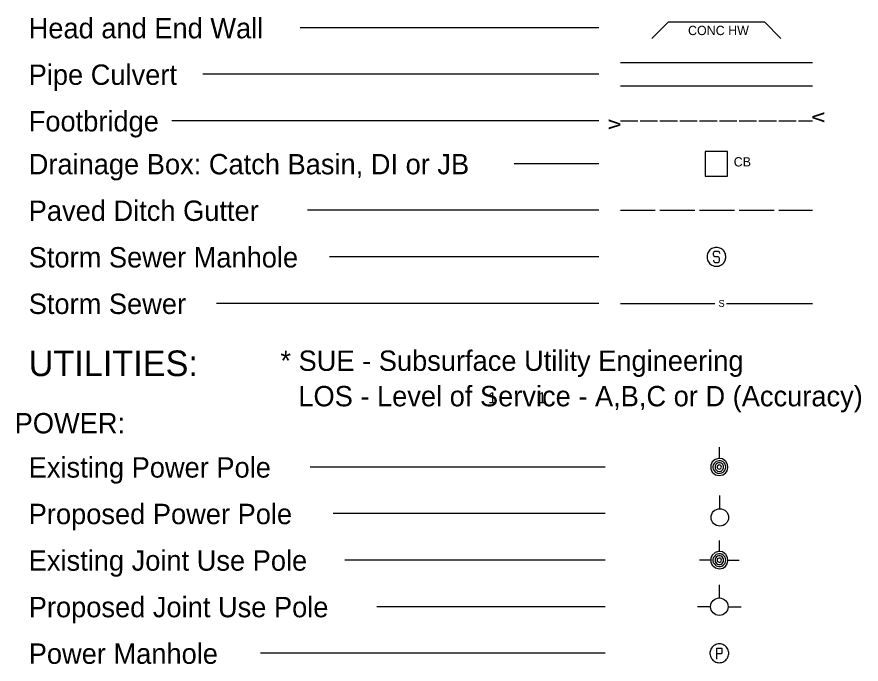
# Model space of a CAD drawing. Extents: x 811137 to 813186, y 647386 to 648494.
# Drawn here: x 812023.6 to 812389.6, y 647926.9 to 648207.5 of the extents above; entities that cross this region are included whole.
import ezdxf

# ---------------------------------------------------------------- set-up
doc = ezdxf.new("R2010")
doc.units = 0
doc.layers.add('Default', color=7, linetype='Continuous')
doc.layers.add('Sheet_Symbology', color=7, linetype='Continuous')

msp = doc.modelspace()

# ---------------------------------------------------------------- linework, layer by layer
at = {"layer": 'Sheet_Symbology'}
for p, q in [((812275.83, 648202.78), (812146.38, 648202.78)), ((812298.88, 648198.17), (812306.02, 648205.3)), ((812306.02, 648205.3), (812347.64, 648205.3)), ((812347.64, 648205.3), (812354.78, 648198.17)), ((812285.21, 648187.65), (812368.45, 648187.65)), ((812275.83, 648182.6), (812104.12, 648182.6)), ((812285.21, 648177.56), (812368.45, 648177.56)), ((812275.83, 648162.42), (812090.71, 648162.42)), ((812285.21, 648162.42), (812292.78, 648162.42)), ((812293.79, 648162.42), (812301.35, 648162.42)), ((812302.36, 648162.42), (812309.93, 648162.42)), ((812310.94, 648162.42), (812318.5, 648162.42)), ((812319.51, 648162.42), (812327.08, 648162.42)), ((812328.09, 648162.42), (812335.66, 648162.42)), ((812336.67, 648162.42), (812344.23, 648162.42)), ((812345.24, 648162.42), (812352.81, 648162.42)), ((812353.82, 648162.42), (812361.38, 648162.42)), ((812362.39, 648162.42), (812368.45, 648162.42)), ((812275.83, 648143.82), (812239.21, 648143.82)), ((812275.83, 648123.64), (812149.52, 648123.64)), ((812285.21, 648123.64), (812300.34, 648123.64)), ((812302.36, 648123.64), (812317.5, 648123.64)), ((812319.51, 648123.64), (812334.65, 648123.64)), ((812336.67, 648123.64), (812351.8, 648123.64)), ((812353.82, 648123.64), (812368.45, 648123.64)), ((812275.83, 648103.46), (812159.12, 648103.46)), ((812325.62, 648104.19), (812325.62, 648105.27)), ((812326.34, 648105.99), (812327.42, 648105.99)), ((812327.42, 648103.5), (812326.34, 648103.5)), ((812328.11, 648105.27), (812328.11, 648104.91)), ((812325.62, 648102.06), (812325.62, 648101.69)), ((812326.34, 648101.01), (812327.42, 648101.01)), ((812328.11, 648101.69), (812328.11, 648102.81)), ((812275.83, 648083.29), (812110.16, 648083.29)), ((812285.21, 648083.29), (812326.1, 648083.29)), ((812331.14, 648083.29), (812368.45, 648083.29)), ((812328.09, 648016.08), (812328.09, 648020.92)), ((812278.64, 648012.36), (812150.64, 648012.36)), ((812328.3, 647994.31), (812328.3, 647999.98)), ((812278.64, 647992.18), (812160.61, 647992.18)), ((812328.09, 647975.72), (812328.09, 647980.56)), ((812278.64, 647972), (812165.73, 647972)), ((812324.36, 647972), (812319.52, 647972)), ((812331.81, 647972), (812336.65, 647972)), ((812328.09, 647955.62), (812328.09, 647961.29)), ((812278.64, 647951.82), (812179.54, 647951.82)), ((812324.31, 647951.83), (812318.63, 647951.83)), ((812331.87, 647951.83), (812337.55, 647951.83)), ((812278.64, 647931.64), (812129.16, 647931.64)), ((812328.91, 647931.44), (812327.07, 647931.44)), ((812329.24, 647933.51), (812329.24, 647931.77))]:
    msp.add_line(p, q, dxfattribs=at)
for points in [[(812321.97, 648138.46), (812331.67, 648138.46), (812331.67, 648149.19), (812321.97, 648149.19)], [(812328.09, 648008.63), (812329.65, 648008.93), (812330.7, 648009.67), (812331.52, 648010.72), (812331.81, 648012.13), (812331.66, 648013.47), (812330.92, 648014.81), (812329.43, 648015.93), (812327.72, 648016.08), (812326.23, 648015.63), (812325.04, 648014.59), (812324.44, 648013.18), (812324.44, 648011.54), (812325.04, 648010.12), (812326.38, 648009)], [(812328.09, 647968.27), (812329.65, 647968.57), (812330.7, 647969.32), (812331.52, 647970.36), (812331.81, 647971.77), (812331.66, 647973.12), (812330.92, 647974.46), (812329.43, 647975.57), (812327.72, 647975.72), (812326.23, 647975.27), (812325.04, 647974.23), (812324.44, 647972.82), (812324.44, 647971.18), (812325.04, 647969.76), (812326.38, 647968.64)]]:
    msp.add_lwpolyline(points, close=True, dxfattribs=at)
for points in [[(812326.83, 648107.56), (812326.3, 648107.53), (812325.81, 648107.43), (812325.32, 648107.27), (812324.86, 648107.04), (812324.44, 648106.77), (812324.04, 648106.45), (812323.68, 648106.05), (812323.39, 648105.66), (812323.12, 648105.2), (812322.96, 648104.71), (812322.83, 648104.22), (812322.76, 648103.73), (812322.76, 648103.2), (812322.83, 648102.71), (812322.96, 648102.19), (812323.12, 648101.73), (812323.39, 648101.27), (812323.68, 648100.88), (812324.04, 648100.48), (812324.44, 648100.16), (812324.86, 648099.89), (812325.32, 648099.66), (812325.81, 648099.5), (812326.34, 648099.4), (812326.83, 648099.37), (812327.35, 648099.4), (812327.84, 648099.5), (812328.34, 648099.66), (812328.79, 648099.89), (812329.22, 648100.16), (812329.61, 648100.48), (812329.98, 648100.88), (812330.27, 648101.27), (812330.53, 648101.73), (812330.7, 648102.22), (812330.83, 648102.71), (812330.89, 648103.2), (812330.89, 648103.73), (812330.83, 648104.22), (812330.7, 648104.74), (812330.53, 648105.2), (812330.27, 648105.66), (812329.98, 648106.05), (812329.61, 648106.45), (812329.22, 648106.77), (812328.79, 648107.04), (812328.34, 648107.27), (812327.84, 648107.43), (812327.32, 648107.53), (812326.83, 648107.56)], [(812325.62, 648105.27), (812325.68, 648105.5), (812325.78, 648105.69), (812325.91, 648105.82), (812326.11, 648105.92), (812326.34, 648105.99)], [(812326.34, 648103.5), (812326.11, 648103.53), (812325.91, 648103.63), (812325.78, 648103.79), (812325.68, 648103.99), (812325.62, 648104.19)], [(812327.42, 648105.99), (812327.61, 648105.92), (812327.81, 648105.82), (812327.98, 648105.69), (812328.07, 648105.5), (812328.11, 648105.27)], [(812328.11, 648102.78), (812328.07, 648103.01), (812327.98, 648103.2), (812327.81, 648103.37), (812327.61, 648103.46), (812327.42, 648103.5)], [(812325.62, 648101.73), (812325.68, 648101.5), (812325.78, 648101.3), (812325.91, 648101.14), (812326.11, 648101.04), (812326.34, 648101.01)], [(812327.42, 648101.01), (812327.61, 648101.04), (812327.81, 648101.14), (812327.98, 648101.3), (812328.07, 648101.5), (812328.11, 648101.73)], [(812330.85, 648012.36), (812330.77, 648013.03), (812330.55, 648013.62), (812330.17, 648014.14), (812329.73, 648014.59), (812329.21, 648014.89), (812328.54, 648015.04), (812327.94, 648015.11), (812327.27, 648014.96), (812326.67, 648014.74), (812326.23, 648014.37), (812325.78, 648013.85), (812325.48, 648013.32), (812325.33, 648012.65), (812325.33, 648012.06), (812325.48, 648011.39), (812325.78, 648010.87), (812326.23, 648010.34), (812326.67, 648009.97), (812327.27, 648009.75), (812327.94, 648009.6), (812328.54, 648009.67), (812329.21, 648009.82), (812329.73, 648010.12), (812330.17, 648010.57), (812330.55, 648011.09), (812330.77, 648011.69), (812330.85, 648012.36)], [(812329.95, 648012.36), (812329.88, 648012.88), (812329.65, 648013.4), (812329.28, 648013.77), (812328.84, 648014.07), (812328.39, 648014.22), (812327.79, 648014.22), (812327.34, 648014.07), (812326.9, 648013.77), (812326.53, 648013.4), (812326.3, 648012.88), (812326.23, 648012.36), (812326.3, 648011.83), (812326.53, 648011.31), (812326.9, 648010.94), (812327.34, 648010.64), (812327.79, 648010.49), (812328.39, 648010.49), (812328.84, 648010.64), (812329.28, 648010.94), (812329.65, 648011.31), (812329.88, 648011.83), (812329.95, 648012.36)], [(812328.98, 648012.36), (812328.91, 648012.73), (812328.69, 648013.03), (812328.39, 648013.18), (812328.02, 648013.25), (812327.64, 648013.1), (812327.34, 648012.88), (812327.2, 648012.51), (812327.2, 648012.21), (812327.34, 648011.83), (812327.64, 648011.61), (812328.02, 648011.46), (812328.39, 648011.54), (812328.69, 648011.69), (812328.91, 648011.98), (812328.98, 648012.36)], [(812330.85, 647972), (812330.77, 647972.67), (812330.55, 647973.26), (812330.17, 647973.79), (812329.73, 647974.23), (812329.21, 647974.53), (812328.54, 647974.68), (812327.94, 647974.76), (812327.27, 647974.61), (812326.67, 647974.38), (812326.23, 647974.01), (812325.78, 647973.49), (812325.48, 647972.97), (812325.33, 647972.3), (812325.33, 647971.7), (812325.48, 647971.03), (812325.78, 647970.51), (812326.23, 647969.99), (812326.67, 647969.61), (812327.27, 647969.39), (812327.94, 647969.24), (812328.54, 647969.32), (812329.21, 647969.46), (812329.73, 647969.76), (812330.17, 647970.21), (812330.55, 647970.73), (812330.77, 647971.33), (812330.85, 647972)], [(812329.95, 647972), (812329.88, 647972.52), (812329.65, 647973.04), (812329.28, 647973.41), (812328.84, 647973.71), (812328.39, 647973.86), (812327.79, 647973.86), (812327.34, 647973.71), (812326.9, 647973.41), (812326.53, 647973.04), (812326.3, 647972.52), (812326.23, 647972), (812326.3, 647971.48), (812326.53, 647970.96), (812326.9, 647970.58), (812327.34, 647970.28), (812327.79, 647970.14), (812328.39, 647970.14), (812328.84, 647970.28), (812329.28, 647970.58), (812329.65, 647970.96), (812329.88, 647971.48), (812329.95, 647972)], [(812328.98, 647972), (812328.91, 647972.37), (812328.69, 647972.67), (812328.39, 647972.82), (812328.02, 647972.89), (812327.64, 647972.74), (812327.34, 647972.52), (812327.2, 647972.15), (812327.2, 647971.85), (812327.34, 647971.48), (812327.64, 647971.25), (812328.02, 647971.1), (812328.39, 647971.18), (812328.69, 647971.33), (812328.91, 647971.63), (812328.98, 647972)], [(812328.09, 647935.74), (812327.57, 647935.7), (812327.07, 647935.61), (812326.58, 647935.44), (812326.12, 647935.21), (812325.7, 647934.95), (812325.3, 647934.62), (812324.94, 647934.23), (812324.65, 647933.84), (812324.39, 647933.38), (812324.22, 647932.89), (812324.09, 647932.39), (812324.03, 647931.9), (812324.03, 647931.38), (812324.09, 647930.89), (812324.22, 647930.36), (812324.39, 647929.9), (812324.65, 647929.44), (812324.94, 647929.05), (812325.3, 647928.66), (812325.7, 647928.33), (812326.12, 647928.07), (812326.58, 647927.84), (812327.07, 647927.67), (812327.6, 647927.58), (812328.09, 647927.54), (812328.61, 647927.58), (812329.1, 647927.67), (812329.6, 647927.84), (812330.06, 647928.07), (812330.48, 647928.33), (812330.87, 647928.66), (812331.24, 647929.05), (812331.53, 647929.44), (812331.79, 647929.9), (812331.96, 647930.39), (812332.09, 647930.89), (812332.15, 647931.38), (812332.15, 647931.9), (812332.09, 647932.39), (812331.96, 647932.92), (812331.79, 647933.38), (812331.53, 647933.84), (812331.24, 647934.23), (812330.87, 647934.62), (812330.48, 647934.95), (812330.06, 647935.21), (812329.6, 647935.44), (812329.1, 647935.61), (812328.58, 647935.7), (812328.09, 647935.74)], [(812327.07, 647929.02), (812327.07, 647931.44), (812327.07, 647933.84), (812328.91, 647933.84)], [(812328.91, 647933.84), (812329.04, 647933.8), (812329.14, 647933.74), (812329.2, 647933.64), (812329.24, 647933.51)], [(812329.24, 647931.77), (812329.2, 647931.64), (812329.14, 647931.54), (812329.04, 647931.48), (812328.91, 647931.44)]]:
    msp.add_lwpolyline(points, dxfattribs=at)
for centre in [(812328.3, 647990.52), (812328.09, 647951.82)]:
    msp.add_circle(centre, 3.78, dxfattribs=at)

# ---------------------------------------------------------------- texts
at = {"layer": 'Default'}
for p in [(812227.87, 648040), (812249.49, 648040)]:
    msp.add_text('1', height=4.8, dxfattribs=at).set_placement(p)
at = {"layer": 'Sheet_Symbology'}
for s, height, p in [('Head and End Wall', 8.8282, (812028.67, 648198.19)), ('Pipe Culvert', 8.8282, (812028.67, 648178.02)), ('Footbridge', 8.828, (812028.69, 648157.85)), ('Drainage Box: Catch Basin, DI or JB', 8.8282, (812028.69, 648139.24)), ('Paved Ditch Gutter', 8.8282, (812028.69, 648119.05)), ('Storm Sewer Manhole', 8.8282, (812028.69, 648098.87)), ('Storm Sewer', 8.8282, (812028.69, 648078.7)), ('S', 3.03, (812327.71, 648081.77)), ('UTILITIES:', 11.098, (812028.67, 648051.78)), ('POWER:', 8.828, (812022.6, 648026.95)), ('Existing Power Pole', 8.8282, (812028.69, 648007.78)), ('Proposed Power Pole', 8.8282, (812028.69, 647987.6)), ('Existing Joint Use Pole', 8.8282, (812028.69, 647967.43)), ('Proposed Joint Use Pole', 8.8282, (812028.7, 647947.24)), ('Power Manhole', 8.8282, (812028.7, 647927.06))]:
    msp.add_text(s, height=height, dxfattribs=at).set_placement(p)
for s, height, rotation, p in [('CONC HW', 4.036, 360, (812314.52, 648199.59)), ('v', 6.66, 270.2409, (812368.43, 648166.19)), ('v', 6.66, 89.7591, (812285.2, 648158.65)), ('CB', 4.036, 360, (812334.33, 648142.64)), ('* SUE - Subsurface Utility Engineering', 8.8282, 360, (812137.8, 648054.05)), ('LOS - Level of Service - A,B,C or D (Accuracy) ', 8.8282, 360, (812145.58, 648038.68))]:
    msp.add_text(s, height=height, rotation=rotation, dxfattribs=at).set_placement(p)

doc.saveas('drawing.dxf')
